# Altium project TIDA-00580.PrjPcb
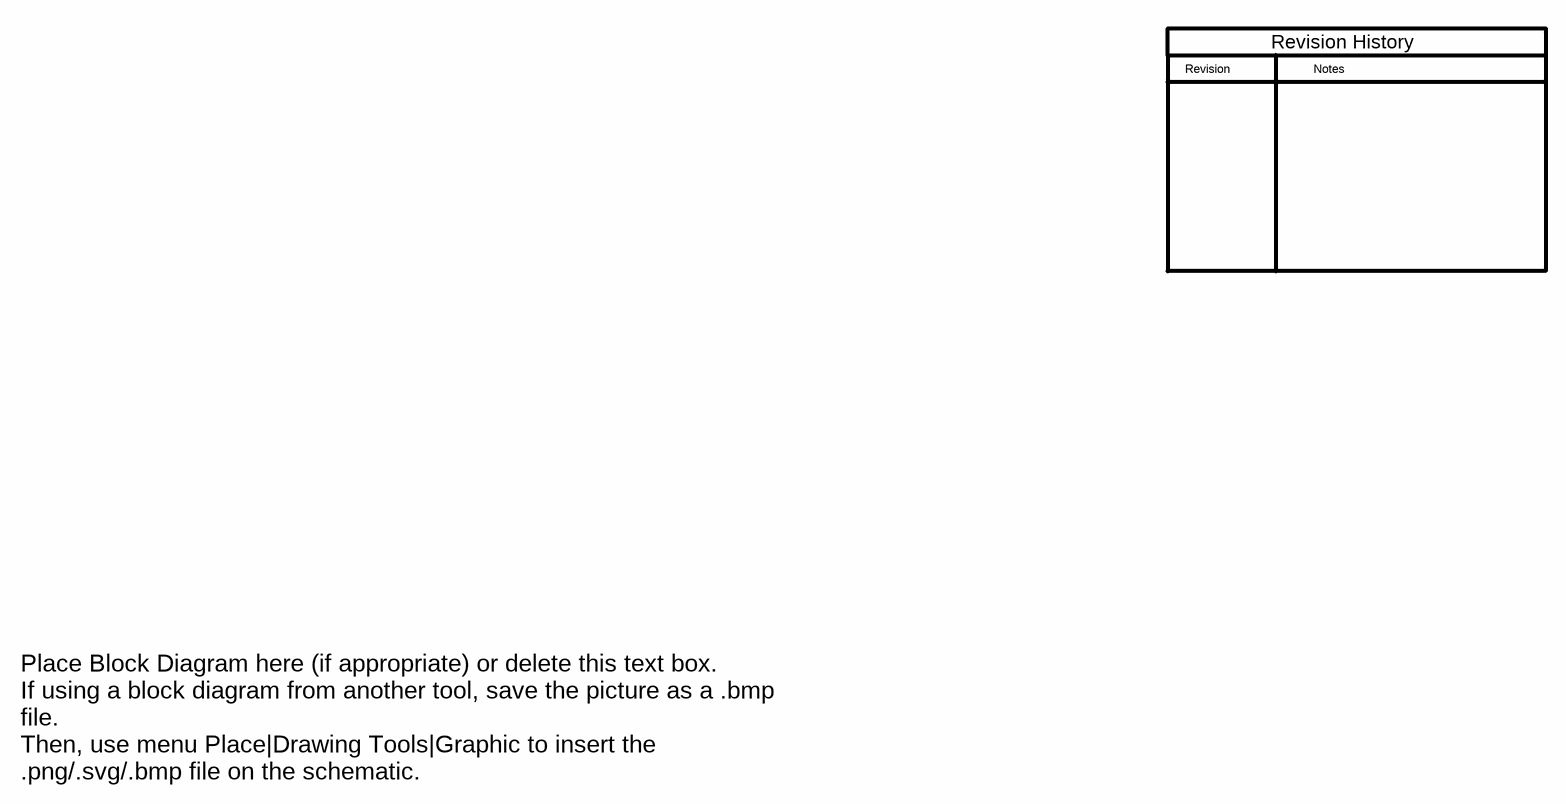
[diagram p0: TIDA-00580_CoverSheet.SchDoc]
CopyrightYear: 2015; EVM_Orderable: N/A; PCB_Layout: Emrys Maier; PCB_Rev: E1; PRJ_Customer: Public Release; PRJ_Engineer: Emrys Maier; PRJ_Number: TIDA-00580; PRJ_Title: Discrete Logic Rotary Quadrature Decoder; SCH_Rev: E1; TechSupport: http://www.ti.com/support; TID: unknown
6 sheets, 77 parts. Net scope: hierarchical (ports join the sheet entries above them; power ports are global).
Board file: TIDA-00580.PcbDoc
Sheets:
  TIDA-00580_CoverSheet.SchDoc
  TIDA-00580_BlankSheet.SchDoc
  TIDA-00580_Hardware.SchDoc
  TIDA-00580_Schematic_Input.SchDoc
  TIDA-00580_Schematic.SchDoc
    Test Interface = TIDA-00580_Schematic_Output.SchDoc

## Sheet TIDA-00580_CoverSheet.SchDoc
size 431 x 279 mm; Date: Not shown in title block; ApprovedBy: Not shown in title block; CheckedBy: Not shown in title block; Author: Not shown in title block; CompanyName: Not shown in title block; Engineer: Not shown in title block; Organization: Not shown in title block; Address1: Not shown in title block; Address2: Not shown in title block; Address3: Not shown in title block; Address4: Not shown in title block; DocumentNumber: 1; Revision: Use project parameter SCH_Rev; SheetNumber: 1; SheetTotal: 3; PageSetup: Record=PageOptions¦CenterHorizontal=True¦CenterVertical=True¦PrintScale=1.00¦XCorrection=1.00¦YCorrection=1.00¦PrintKind=0¦BorderSize=5000000¦LeftOffset=0¦BottomOffset=0¦Orientation=2¦PaperLength=1000¦PaperWidth=1000¦Scale=100¦PaperSource=15¦PrintQuality=600¦MediaType=1¦DitherType=10¦PaperKind=Letter¦PrintScaleMode=1

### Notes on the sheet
- Revision
- Notes
- Revision History
- Place Block Diagram here (if appropriate) or delete this text box.
  If using a block diagram from another tool, save the picture as a .bmp file.
  Then, use menu Place|Drawing Tools|Graphic to insert the .png/.svg/.bmp file on the schematic.

## Sheet TIDA-00580_BlankSheet.SchDoc
size 431 x 279 mm; Date: Not shown in title block; ApprovedBy: Not shown in title block; CheckedBy: Not shown in title block; Author: Not shown in title block; CompanyName: Not shown in title block; Engineer: Not shown in title block; Organization: Not shown in title block; Address1: Not shown in title block; Address2: Not shown in title block; Address3: Not shown in title block; Address4: Not shown in title block; DocumentNumber: 1; Revision: Use project parameter SCH_Rev; SheetNumber: 2; SheetTotal: 3; PageSetup: Record=PageOptions¦CenterHorizontal=True¦CenterVertical=True¦PrintScale=1.00¦XCorrection=1.00¦YCorrection=1.00¦PrintKind=0¦BorderSize=5000000¦LeftOffset=0¦BottomOffset=0¦Orientation=2¦PaperLength=1000¦PaperWidth=1000¦Scale=100¦PaperSource=15¦PrintQuality=600¦MediaType=1¦DitherType=10¦PaperKind=Letter¦PrintScaleMode=1

## Sheet TIDA-00580_Hardware.SchDoc
size 431 x 279 mm; Date: Not shown in title block; ApprovedBy: Not shown in title block; CheckedBy: Not shown in title block; Author: Not shown in title block; CompanyName: Not shown in title block; Engineer: Not shown in title block; Organization: Not shown in title block; Address1: Not shown in title block; Address2: Not shown in title block; Address3: Not shown in title block; Address4: Not shown in title block; DocumentNumber: 1; Revision: Use project parameter SCH_Rev; SheetNumber: 3; SheetTotal: 3; PageSetup: Record=PageOptions¦CenterHorizontal=True¦CenterVertical=True¦PrintScale=1.00¦XCorrection=1.00¦YCorrection=1.00¦PrintKind=0¦BorderSize=5000000¦LeftOffset=0¦BottomOffset=0¦Orientation=2¦PaperLength=1000¦PaperWidth=1000¦Scale=100¦PaperSource=15¦PrintQuality=600¦MediaType=1¦DitherType=10¦PaperKind=Letter¦PrintScaleMode=1
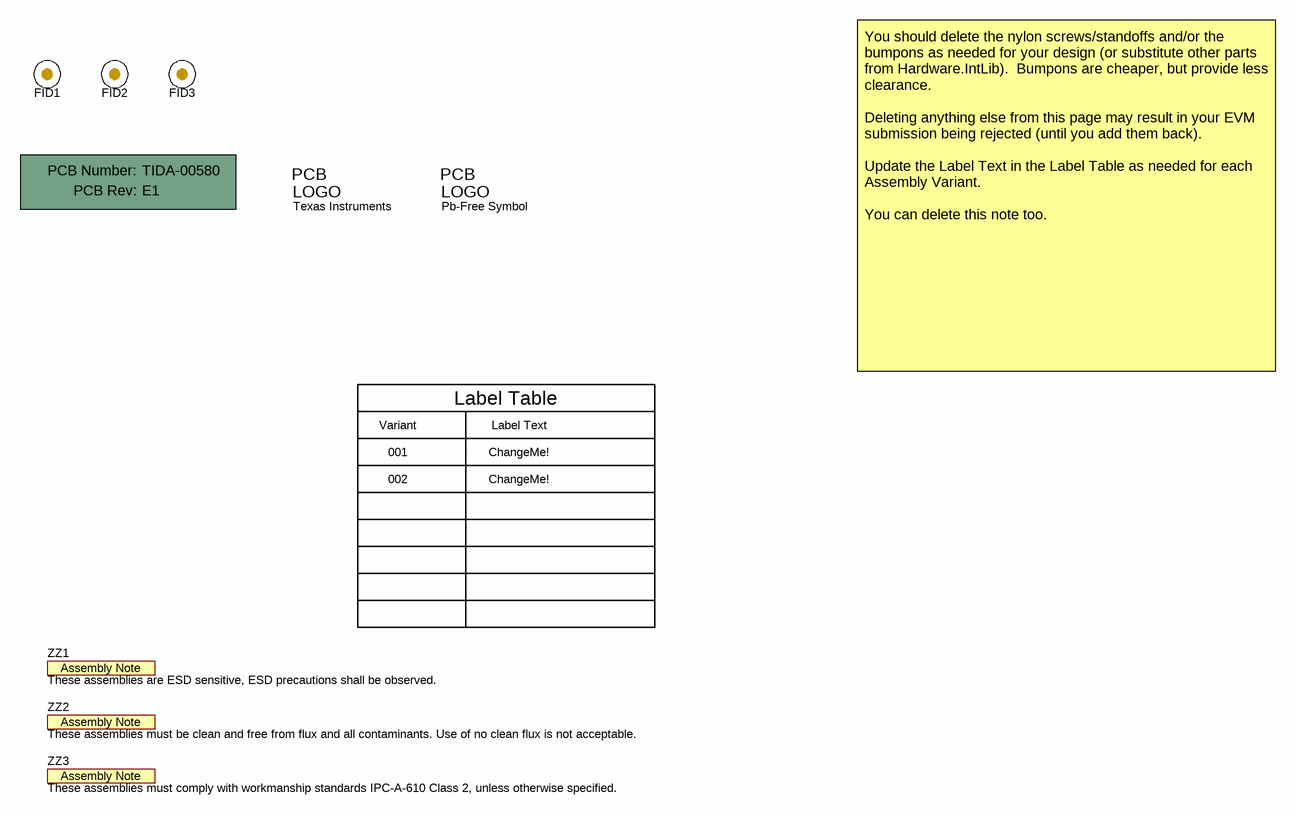
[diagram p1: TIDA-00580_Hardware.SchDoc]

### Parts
!PCB1  Printed Circuit Board  (value not drawn)  (mechanical)
FID1  Fiducial  [Fiducial10-20]  (value not drawn)
FID2  Fiducial  [Fiducial10-20]  (value not drawn)
FID3  Fiducial  [Fiducial10-20]  (value not drawn)
Logo1  Texas Instruments  [TI_Stacked_SolderMask_Small]  (no BOM)
Logo2  Pb-Free Symbol  [Pb-Free_Overlay_Small]  (no BOM)
ZZ1  These assemblies are ESD sensitive, ESD precautions shall be observed.  [AssemblyNote]  (no BOM)
ZZ2  These assemblies must be clean and free from flux and all contaminants. Use of no clean flux is not acceptable.  [AssemblyNote]  (no BOM)
ZZ3  These assemblies must comply with workmanship standards IPC-A-610 Class 2, unless otherwise specified.  [AssemblyNote]  (no BOM)

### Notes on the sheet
- Variant
- Label Table
- Label Text
- You should delete the nylon screws/standoffs and/or the bumpons as needed for your design (or substitute other parts from Hardware.IntLib).  Bumpons are cheaper, but provide less clearance.
  Deleting anything else from this page may result in your EVM submission being rejected (until you add them back).
  Update the Label Text in the Label Table as needed for each Assembly Variant.
  You can delete this note too.
- 001
- 002
- ChangeMe!

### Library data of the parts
!PCB1 = PCB: Manufacturer: Any; PartNumber: TIDA-00580; SymbolCreator: a0412235
FID1-FID3 = Fiducial: Fiducial mark.  There is nothing to buy or mount.; SymbolCreator: codlsc
Logo1 = TI_Logo: Texas Instrument Corporate Signature; SymbolCreator: codlsc
Logo2 = Pb-Free: SymbolCreator: a0412235
ZZ1-ZZ3 = AssemblyNote: SymbolCreator: codlsc

## Sheet TIDA-00580_Schematic_Input.SchDoc
size 431 x 279 mm; Date: Not shown in title block; ApprovedBy: Not shown in title block; CheckedBy: Not shown in title block; Author: Not shown in title block; CompanyName: Not shown in title block; Engineer: Not shown in title block; Organization: Not shown in title block; Address1: Not shown in title block; Address2: Not shown in title block; Address3: Not shown in title block; Address4: Not shown in title block; DocumentNumber: 1; Revision: Use project parameter SCH_Rev; SheetNumber: 2; SheetTotal: 3; PageSetup: Record=PageOptions¦CenterHorizontal=True¦CenterVertical=True¦PrintScale=1.00¦XCorrection=1.00¦YCorrection=1.00¦PrintKind=0¦BorderSize=5000000¦LeftOffset=0¦BottomOffset=0¦Orientation=2¦PaperLength=1000¦PaperWidth=1000¦Scale=100¦PaperSource=15¦PrintQuality=600¦MediaType=1¦DitherType=10¦PaperKind=Letter¦PrintScaleMode=1

## Sheet TIDA-00580_Schematic.SchDoc
size 431 x 279 mm; Date: Not shown in title block; ApprovedBy: Not shown in title block; CheckedBy: Not shown in title block; Author: Not shown in title block; CompanyName: Not shown in title block; Engineer: Not shown in title block; Organization: Not shown in title block; Address1: Not shown in title block; Address2: Not shown in title block; Address3: Not shown in title block; Address4: Not shown in title block; DocumentNumber: 1; Revision: Use project parameter SCH_Rev; SheetNumber: 2; SheetTotal: 3; PageSetup: Record=PageOptions¦CenterHorizontal=True¦CenterVertical=True¦PrintScale=0.64¦XCorrection=1.00¦YCorrection=1.00¦PrintKind=0¦BorderSize=5000000¦LeftOffset=0¦BottomOffset=0¦Orientation=2¦PaperLength=1000¦PaperWidth=1000¦Scale=100¦PaperSource=15¦PrintQuality=600¦MediaType=1¦DitherType=10¦PrintScaleMode=1¦PaperKind=Letter
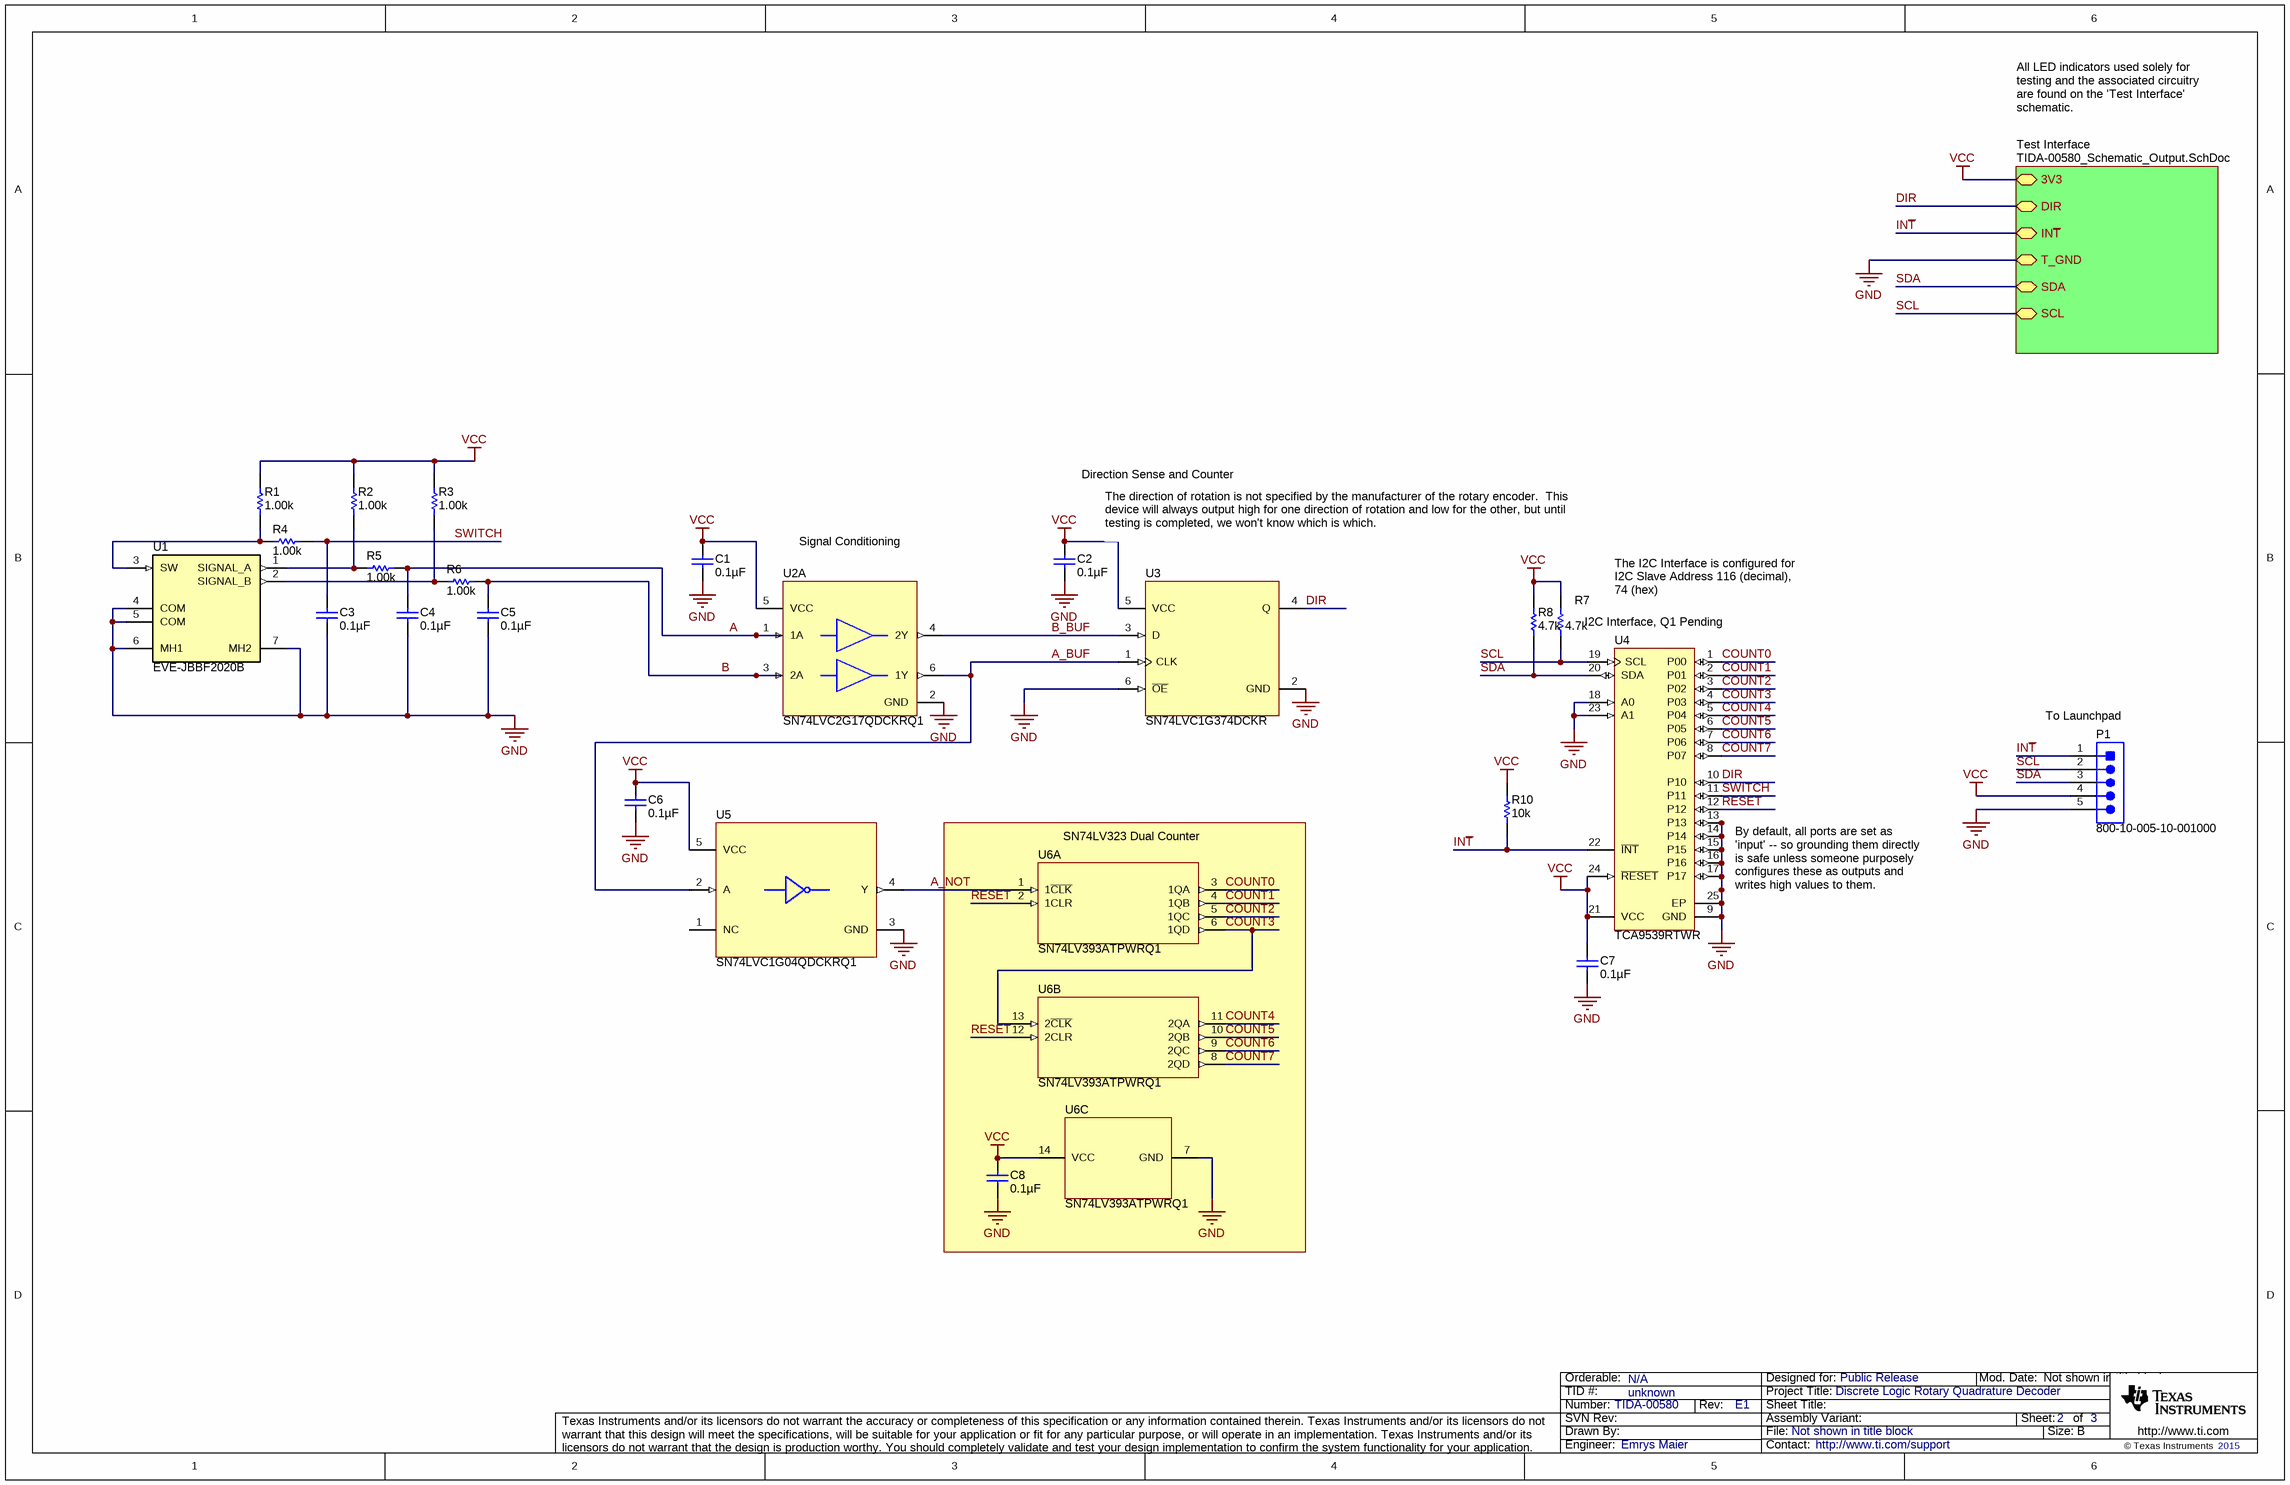
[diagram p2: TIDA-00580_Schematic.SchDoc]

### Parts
(Parts that share a designator on the sheet are numbered #1, #2 ... from top to bottom, then left to right.)
C1  ValueDisplayed: 0.1µF  [0603]  (hidden comment: 0603YC104JAT2A)
C2  ValueDisplayed: 0.1µF  [0603]  (hidden comment: 0603YC104JAT2A)
C3  ValueDisplayed: 0.1µF  [0603]  (hidden comment: 0603YC104JAT2A)
C4  ValueDisplayed: 0.1µF  [0603]  (hidden comment: 0603YC104JAT2A)
C5  ValueDisplayed: 0.1µF  [0603]  (hidden comment: 0603YC104JAT2A)
C6  ValueDisplayed: 0.1µF  [0603]  (hidden comment: 0603YC104JAT2A)
C7  ValueDisplayed: 0.1µF  [0603]  (hidden comment: 0603YC104JAT2A)
C8  ValueDisplayed: 0.1µF  [0603]  (hidden comment: 0603YC104JAT2A)
P1  800-10-005-10-001000  [Mill-Max_800-10-005-10-001000]
R1  ValueDisplayed: 1.00k  [0402]  (hidden comment: CRCW04021K00FKED)
R2  ValueDisplayed: 1.00k  [0402]  (hidden comment: CRCW04021K00FKED)
R3  ValueDisplayed: 1.00k  [0402]  (hidden comment: CRCW04021K00FKED)
R4  ValueDisplayed: 1.00k  [0402]  (hidden comment: CRCW04021K00FKED)
R5  ValueDisplayed: 1.00k  [0402]  (hidden comment: CRCW04021K00FKED)
R6  ValueDisplayed: 1.00k  [0402]  (hidden comment: CRCW04021K00FKED)
R7  ValueDisplayed: 4.7k  [0402]  (hidden comment: CRCW04024K70JNED)
R8  ValueDisplayed: 4.7k  [0402]  (hidden comment: CRCW04024K70JNED)
R10  ValueDisplayed: 10k  [0402]  (hidden comment: CRCW040210K0JNED)
U1  EVE-JBBF2020B  [Panasonic_EVE-JBBF2020B]
U2  SN74LVC2G17QDCKRQ1  [DCK0006A_N]  (part A of 2)
U3  SN74LVC1G374DCKR  [DCK0006A_N]
U4#1  TCA9539RTWR  [RTW0024B]
U5  SN74LVC1G04QDCKRQ1  [DCK0005A_N]
U6  SN74LV393ATPWRQ1  [PW0014A_N]  (parts A,B,C of 3)

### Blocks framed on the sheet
SN74LV323 Dual Counter: C8 U6

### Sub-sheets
Test Interface = TIDA-00580_Schematic_Output.SchDoc: 3V3, IN~{T}, DIR, T_GND, SDA, SCL

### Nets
GND: C1.2 C2.2 C3.2 C4.2 C5.2 C6.2 C7.2 C8.2 P1.5 U1.4(COM) U1.5(COM) U1.6(MH1) U1.7(MH2) U2.2(GND) U3.2(GND) U3.6(~{OE}) U4#1.9(GND) U4#1.13(P13) U4#1.14(P14) U4#1.15(P15) U4#1.16(P16) U4#1.17(P17) U4#1.18(A0) U4#1.23(A1) U4#1.25(EP) U5.3(GND) U6.7(GND) ; sheet Test Interface/T_GND
VCC: C1.1 C2.1 C6.1 C7.1 C8.1 P1.4 R1.2 R2.2 R3.2 R7.2 R8.2 R10.2 U2.5(VCC) U3.5(VCC) U4#1.21(VCC) U4#1.24(~{RESET}) U5.5(VCC) U6.14(VCC) ; sheet Test Interface/3V3  [project net 3V3]
IN~{T}: P1.1 R10.1 U4#1.22(~{INT}) ; sheet Test Interface/IN~{T}
A: C4.1 R5.1 U2.1(1A)
A_BUF: U2.6(1Y) U3.1(CLK) U5.2(A)
A_NOT: U5.4(Y) U6.1(1~{CLK})
B: C5.1 R6.1 U2.3(2A)
B_BUF: U2.4(2Y) U3.3(D)
COUNT0: U4#1.1(P00) U6.3(1QA)
COUNT1: U4#1.2(P01) U6.4(1QB)
COUNT2: U4#1.3(P02) U6.5(1QC)
COUNT3: U4#1.4(P03) U6.6(1QD) U6.13(2~{CLK})
COUNT4: U4#1.5(P04) U6.11(2QA)
COUNT5: U4#1.6(P05) U6.10(2QB)
COUNT6: U4#1.7(P06) U6.9(2QC)
COUNT7: U4#1.8(P07) U6.8(2QD)
DIR: U3.4(Q) U4#1.10(P10) ; sheet Test Interface/DIR
RESET: U4#1.12(P12) U6.2(1CLR) U6.12(2CLR)
SCL: P1.2 R7.1 U4#1.19(SCL) ; sheet Test Interface/SCL
SDA: P1.3 R8.1 U4#1.20(SDA) ; sheet Test Interface/SDA
SWITCH: C3.1 R4.1 U4#1.11(P11)
NetR1_1: R1.1 R4.2 U1.3(SW)
NetR2_1: R2.1 R5.2 U1.1(SIGNAL_A)
NetR3_1: R3.1 R6.2 U1.2(SIGNAL_B)

Not connected (* = marked no-connect by the designer): U5 1(NC)

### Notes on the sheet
- All LED indicators used solely for testing and the associated circuitry are found on the 'Test Interface' schematic.
- Direction Sense and Counter
- Signal Conditioning
- The direction of rotation is not specified by the manufacturer of the rotary encoder.  This device will always output high for one direction of rotation and low for the other, but until testing is completed, we won't know which is which.
- The I2C Interface is configured for I2C Slave Address 116 (decimal), 74 (hex)
- (near R7) I2C Interface, Q1 Pending
- (near P1) To Launchpad
- (near U4#1) By default, all ports are set as 'input' -- so grounding them directly is safe unless someone purposely configures these as outputs and writes high values to them.

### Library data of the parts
C1-C8 = 0603YC104JAT2A: CAP, CERM, 0.1 µF, 16 V, +/- 5%, X7R, 0603; Manufacturer: AVX; Polarized: N; CompType: Capacitor; Value: 0.1uF; U/M: EA; Cap_F: 0.0000001; Tolerance_%: 5; ESR_ohm: 0.039; Value1: 0.039 ohm; VDC_V: 16; Value2: 16V; TaMin_C: -55; TaMax_C: 125
P1 = 800-10-005-10-001000: Header, 100mil, 5x1, TH; Manufacturer: Mill-Max; SymbolCreator: a0412235; U/M: EA
R1-R6 = CRCW04021K00FKED: RES, 1.00 k, 1%, 0.063 W, 0402; Manufacturer: Vishay-Dale; CompType: Resistor; Value: 1.00k; Res_ohm: 1000; Value_Code: 1k00; Tolerance_%: 1; Power_W: 0.063; Value2: 0.063W; VDC_V: 50; TempCo: 100 ppm/C; EIA_Code: E96; U/M: EA
R7 R8 = CRCW04024K70JNED: RES, 4.7 k, 5%, 0.063 W, 0402; Manufacturer: Vishay-Dale; CompType: Resistor; Value: 4.7k; Res_ohm: 4700; Value_Code: 4k70; Tolerance_%: 5; Power_W: 0.063; Value2: 0.063W; VDC_V: 50; TempCo: 200 ppm/C; EIA_Code: E24; U/M: EA
R10 = CRCW040210K0JNED: RES, 10 k, 5%, 0.063 W, 0402; Manufacturer: Vishay-Dale; CompType: Resistor; Value: 10k; Res_ohm: 10000; Value_Code: 10k0; Tolerance_%: 5; Power_W: 0.063; Value2: 0.063W; VDC_V: 50; TempCo: 200 ppm/C; EIA_Code: E24; U/M: EA
U1 = EVE-JBBF2020B: ENCODER ROTARY 12MM 20PPR W/SW, TH; Manufacturer: Panasonic; SymbolCreator: Altium
U2 = SN74LVC2G17QDCKRQ1: Dual Schmitt Trigger Buffer, DCK0006A; Manufacturer: Texas Instruments; SymbolCreator: Altium; CompType: IC; U/M: EA
U3 = SN74LVC1G374DCKR: Single D-Type Flip-Flop With 3-State Output, DCK0006A; Manufacturer: Texas Instruments; SymbolCreator: Altium; CompType: IC; U/M: EA
U4#1 = TCA9539RTWR: Remote 16-Bit I2C and SMBus, Low-Power I/O Expander with Interrupt Output, Reset & Config. Register, 1.65 to 5.5 V, -40 to 85 degC, 24-pin QFN (RTW), Green (RoHS & no Sb/Br); Manufacturer: Texas Instruments; Alternate Manufacturer: None; Alternate PartNumber: Equivalent; SubFamily: I2C IO Expander; Interrupt Output: Yes; Max Frequency(kHz): 400; I2C Address: 1110 1xx; # of I/Os: 16
U5 = SN74LVC1G04DCKR: Single Inverter Gate, DCK0005A; Manufacturer: Texas Instruments; SymbolCreator: a0411947; CompType: IC; U/M: EA
U6 = SN74LV393ATPWRQ1: DUAL 4-BIT BINARY COUNTER, PW0014A; Manufacturer: Texas Instruments; SymbolCreator: Altium; CompType: IC; U/M: EA

## Sheet TIDA-00580_Schematic_Output.SchDoc
size 431 x 279 mm; Date: Not shown in title block; ApprovedBy: Not shown in title block; CheckedBy: Not shown in title block; Author: Not shown in title block; CompanyName: Not shown in title block; Engineer: Not shown in title block; Organization: Not shown in title block; Address1: Not shown in title block; Address2: Not shown in title block; Address3: Not shown in title block; Address4: Not shown in title block; DocumentNumber: 1; Revision: Use project parameter SCH_Rev; SheetNumber: 2; SheetTotal: 3; PageSetup: Record=PageOptions¦CenterHorizontal=True¦CenterVertical=True¦PrintScale=0.64¦XCorrection=1.00¦YCorrection=1.00¦PrintKind=0¦BorderSize=5000000¦LeftOffset=0¦BottomOffset=0¦Orientation=2¦PaperLength=1000¦PaperWidth=1000¦Scale=100¦PaperSource=15¦PrintQuality=600¦MediaType=1¦DitherType=10¦PrintScaleMode=1¦PaperKind=Letter
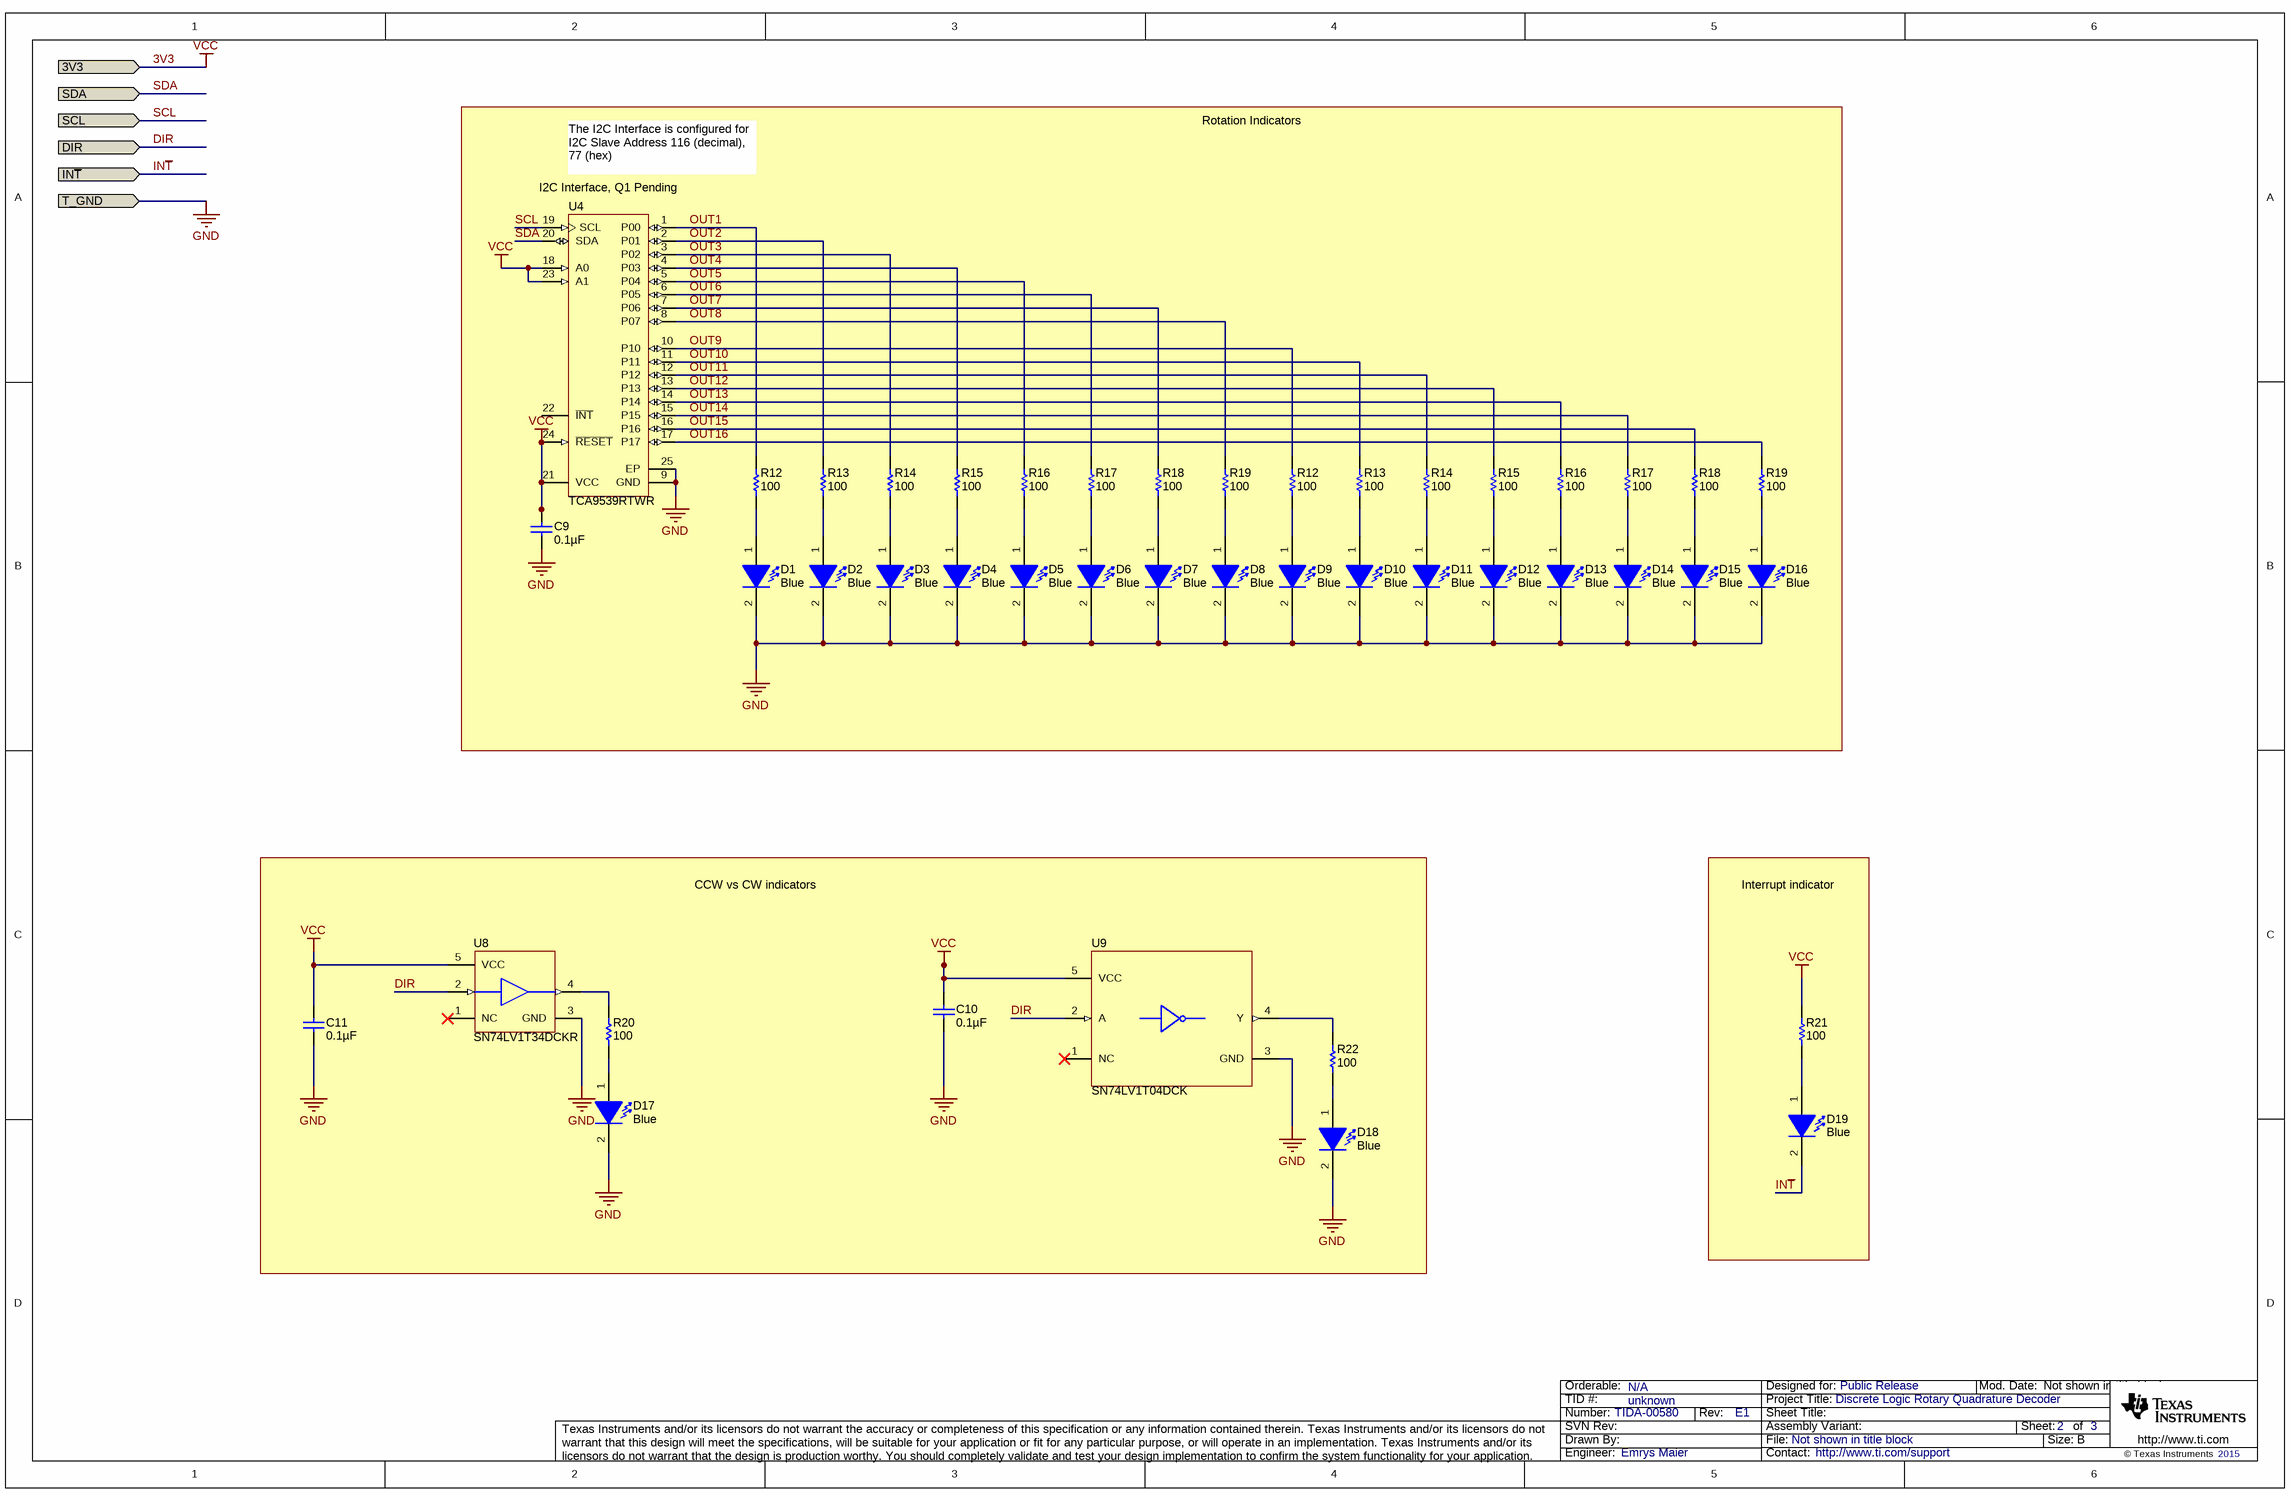
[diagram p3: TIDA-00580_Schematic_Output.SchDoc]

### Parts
(Parts that share a designator on the sheet are numbered #1, #2 ... from top to bottom, then left to right.)
C9  ValueDisplayed: 0.1µF  [0603]  (hidden comment: 0603YC104JAT2A)
C10  ValueDisplayed: 0.1µF  [0603]  (hidden comment: 0603YC104JAT2A)
C11  ValueDisplayed: 0.1µF  [0603]  (hidden comment: 0603YC104JAT2A)
D1  value Blue  [LB Q39G_BLUE]  (hidden comment: LB Q39G-L2N2-35-1)
D2  value Blue  [LB Q39G_BLUE]  (hidden comment: LB Q39G-L2N2-35-1)
D3  value Blue  [LB Q39G_BLUE]  (hidden comment: LB Q39G-L2N2-35-1)
D4  value Blue  [LB Q39G_BLUE]  (hidden comment: LB Q39G-L2N2-35-1)
D5  value Blue  [LB Q39G_BLUE]  (hidden comment: LB Q39G-L2N2-35-1)
D6  value Blue  [LB Q39G_BLUE]  (hidden comment: LB Q39G-L2N2-35-1)
D7  value Blue  [LB Q39G_BLUE]  (hidden comment: LB Q39G-L2N2-35-1)
D8  value Blue  [LB Q39G_BLUE]  (hidden comment: LB Q39G-L2N2-35-1)
D9  value Blue  [LB Q39G_BLUE]  (hidden comment: LB Q39G-L2N2-35-1)
D10  value Blue  [LB Q39G_BLUE]  (hidden comment: LB Q39G-L2N2-35-1)
D11  value Blue  [LB Q39G_BLUE]  (hidden comment: LB Q39G-L2N2-35-1)
D12  value Blue  [LB Q39G_BLUE]  (hidden comment: LB Q39G-L2N2-35-1)
D13  value Blue  [LB Q39G_BLUE]  (hidden comment: LB Q39G-L2N2-35-1)
D14  value Blue  [LB Q39G_BLUE]  (hidden comment: LB Q39G-L2N2-35-1)
D15  value Blue  [LB Q39G_BLUE]  (hidden comment: LB Q39G-L2N2-35-1)
D16  value Blue  [LB Q39G_BLUE]  (hidden comment: LB Q39G-L2N2-35-1)
D17  value Blue  [LB Q39G_BLUE]  (hidden comment: LB Q39G-L2N2-35-1)
D18  value Blue  [LB Q39G_BLUE]  (hidden comment: LB Q39G-L2N2-35-1)
D19  value Blue  [LB Q39G_BLUE]  (hidden comment: LB Q39G-L2N2-35-1)
R12#1  ValueDisplayed: 100  [0603]  (hidden comment: CRCW0603100RJNEA)
R12#2  ValueDisplayed: 100  [0603]  (hidden comment: CRCW0603100RJNEA)
R13#1  ValueDisplayed: 100  [0603]  (hidden comment: CRCW0603100RJNEA)
R13#2  ValueDisplayed: 100  [0603]  (hidden comment: CRCW0603100RJNEA)
R14#1  ValueDisplayed: 100  [0603]  (hidden comment: CRCW0603100RJNEA)
R14#2  ValueDisplayed: 100  [0603]  (hidden comment: CRCW0603100RJNEA)
R15#1  ValueDisplayed: 100  [0603]  (hidden comment: CRCW0603100RJNEA)
R15#2  ValueDisplayed: 100  [0603]  (hidden comment: CRCW0603100RJNEA)
R16#1  ValueDisplayed: 100  [0603]  (hidden comment: CRCW0603100RJNEA)
R16#2  ValueDisplayed: 100  [0603]  (hidden comment: CRCW0603100RJNEA)
R17#1  ValueDisplayed: 100  [0603]  (hidden comment: CRCW0603100RJNEA)
R17#2  ValueDisplayed: 100  [0603]  (hidden comment: CRCW0603100RJNEA)
R18#1  ValueDisplayed: 100  [0603]  (hidden comment: CRCW0603100RJNEA)
R18#2  ValueDisplayed: 100  [0603]  (hidden comment: CRCW0603100RJNEA)
R19#1  ValueDisplayed: 100  [0603]  (hidden comment: CRCW0603100RJNEA)
R19#2  ValueDisplayed: 100  [0603]  (hidden comment: CRCW0603100RJNEA)
R20  ValueDisplayed: 100  [0603]  (hidden comment: CRCW0603100RJNEA)
R21  ValueDisplayed: 100  [0603]  (hidden comment: CRCW0603100RJNEA)
R22  ValueDisplayed: 100  [0603]  (hidden comment: CRCW0603100RJNEA)
U4#2  TCA9539RTWR  [RTW0024B]
U8  SN74LV1T34DCKR  [DCK0005A_N]
U9  SN74LV1T04DCK  [DCK0005A_N]

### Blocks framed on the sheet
CCW vs CW indicators: C10 C11 D17 D18 R20 R22 U8 U9
Interrupt indicator: D19 R21

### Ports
3V3 (in), DIR (in), IN~{T} (in), SCL (in), SDA (in), T_GND (in)

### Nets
3V3: C9.1 C10.1 C11.1 R21.2 U4#2.18(A0) U4#2.21(VCC) U4#2.23(A1) U4#2.24(~{RESET}) U8.5(VCC) U9.5(VCC) ; port 3V3  [also labelled VCC]
GND: C9.2 C10.2 C11.2 D1.2(K) D2.2(K) D3.2(K) D4.2(K) D5.2(K) D6.2(K) D7.2(K) D8.2(K) D9.2(K) D10.2(K) D11.2(K) D12.2(K) D13.2(K) D14.2(K) D15.2(K) D16.2(K) D17.2(K) D18.2(K) U4#2.9(GND) U4#2.25(EP) U8.3(GND) U9.3(GND) ; port T_GND
IN~{T}: D19.2(K) ; port IN~{T}
DIR: U8.2(A) U9.2(A) ; port DIR
OUT1: R12#1.2 U4#2.1(P00)
OUT2: R13#1.2 U4#2.2(P01)
OUT3: R14#1.2 U4#2.3(P02)
OUT4: R15#1.2 U4#2.4(P03)
OUT5: R16#1.2 U4#2.5(P04)
OUT6: R17#1.2 U4#2.6(P05)
OUT7: R18#1.2 U4#2.7(P06)
OUT8: R19#1.2 U4#2.8(P07)
OUT9: R12#2.2 U4#2.10(P10)
OUT10: R13#2.2 U4#2.11(P11)
OUT11: R14#2.2 U4#2.12(P12)
OUT12: R15#2.2 U4#2.13(P13)
OUT13: R16#2.2 U4#2.14(P14)
OUT14: R17#2.2 U4#2.15(P15)
OUT15: R18#2.2 U4#2.16(P16)
OUT16: R19#2.2 U4#2.17(P17)
SCL: U4#2.19(SCL) ; port SCL
SDA: U4#2.20(SDA) ; port SDA
NetD1_1: D1.1(A) R12#1.1
NetD2_1: D2.1(A) R13#1.1
NetD3_1: D3.1(A) R14#1.1
NetD4_1: D4.1(A) R15#1.1
NetD5_1: D5.1(A) R16#1.1
NetD6_1: D6.1(A) R17#1.1
NetD7_1: D7.1(A) R18#1.1
NetD8_1: D8.1(A) R19#1.1
NetD9_1: D9.1(A) R12#2.1
NetD10_1: D10.1(A) R13#2.1
NetD11_1: D11.1(A) R14#2.1
NetD12_1: D12.1(A) R15#2.1
NetD13_1: D13.1(A) R16#2.1
NetD14_1: D14.1(A) R17#2.1
NetD15_1: D15.1(A) R18#2.1
NetD16_1: D16.1(A) R19#2.1
NetD17_1: D17.1(A) R20.1
NetD18_1: D18.1(A) R22.1
NetD19_1: D19.1(A) R21.1
NetR20_2: R20.2 U8.4(Y)
NetR22_2: R22.2 U9.4(Y)

Not connected (* = marked no-connect by the designer): U4#2 22(~{INT}); U8 1(NC)*; U9 1(NC)*

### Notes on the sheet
- The I2C Interface is configured for I2C Slave Address 116 (decimal), 77 (hex)
- Rotation Indicators
- (near U4#2) I2C Interface, Q1 Pending

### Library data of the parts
C9-C11 = 0603YC104JAT2A: as C1 on sheet TIDA-00580_Schematic
D1-D19 = LB Q39G-L2N2-35-1: LED, Blue, SMD; Manufacturer: OSRAM; Vf_V: 2.85; Value2: 2.85V; Io_A: 0.15; Tjmax_C: 95; Value1: W; U/M: EA
R12#1 R12#2 R13#1 R13#2 R14#1 R14#2 R15#1 R15#2 R16#1 R16#2 R17#1 R17#2 R18#1 R18#2 R19#1 R19#2 R20-R22 = CRCW0603100RJNEA: RES, 100, 5%, 0.1 W, 0603; Manufacturer: Vishay-Dale; CompType: Resistor; Value: 100; Value_Code: 100R; Tolerance_%: 5; Power_W: 0.1; Value2: 0.1W; VDC_V: 75; TempCo: 200 ppm/C; EIA_Code: E24; U/M: EA
U4#2 = TCA9539RTWR: as U4#1 on sheet TIDA-00580_Schematic
U8 = SN74LV1T34DCKR: Single Power Supply Single Buffer GATE CMOS Logic Level Shifter, DCK0005A; Manufacturer: Texas Instruments; SymbolCreator: Altium; CompType: IC; U/M: EA
U9 = SN74LV1T04DCK: SN74LV1T04 Single Power Supply Inverter Gate CMOS Logic Level Shifter, DCK0005A; Manufacturer: Texas Instruments; SymbolCreator: a0411947; CompType: IC; U/M: EA

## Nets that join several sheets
3V3: TIDA-00580_Schematic (18 pins), TIDA-00580_Schematic_Output (10 pins)
GND: TIDA-00580_Schematic (27 pins), TIDA-00580_Schematic_Output (25 pins)
IN~{T}: TIDA-00580_Schematic (P1.1 R10.1 U4#1.22), TIDA-00580_Schematic_Output (D19.2)
DIR: TIDA-00580_Schematic (U3.4 U4#1.10), TIDA-00580_Schematic_Output (U8.2 U9.2)
SCL: TIDA-00580_Schematic (P1.2 R7.1 U4#1.19), TIDA-00580_Schematic_Output (U4#2.19)
SDA: TIDA-00580_Schematic (P1.3 R8.1 U4#1.20), TIDA-00580_Schematic_Output (U4#2.20)

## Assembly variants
001: not fitted FID1 FID2 FID3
